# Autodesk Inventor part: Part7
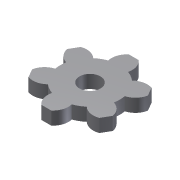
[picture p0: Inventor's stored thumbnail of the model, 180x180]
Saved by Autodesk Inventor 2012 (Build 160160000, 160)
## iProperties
Shininess: 77.0
Angle Display Precision: 2
Document Length Units: 11269
Document Angle Units: 11279
Document Time Units: 11290
Document Mass Units: 11283
Document Length Units Precision: 3
Document Angle Units Precision: 2
Created: 2002-01
Part Number: Part7
Document SubType Name: Modeling
Designer: ***
Density: 1 g/cm^3
Material: Default
Density: 0.0
Volumn: 0.0
Area: 0.0
PropertySet Name: Model Information
Control State: 0
Master: False
Checked Out: False
Author: ***
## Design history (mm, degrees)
sketch "Sketch1"
  geometry: L1 (-3.771, 33.333)-(3.771, 33.333); L2 (-30.753, 13.401)-(-26.982, 19.933); L3 (-30.753, -13.401)-(-26.982, -19.933); L4 (-3.771, -33.333)-(3.771, -33.333); L5 (30.753, 13.401)-(26.982, 19.933); L6 (30.753, -13.401)-(26.982, -19.933); C1 r 8 at (0, 0); A1 r 11.863 centre (3.952, 24.328) between (-3.771, 33.333) and (-7.559, 21.457); A2 r 11.863 centre (-3.952, 24.328) between (7.559, 21.457) and (3.771, 33.333); A3 r 11.863 centre (-19.093, 15.587) between (-30.753, 13.401) and (-22.362, 4.182); A4 r 11.863 centre (-23.045, 8.742) between (-14.803, 17.275) and (-26.982, 19.933); A5 r 22.749 centre (0, 0) between (-7.559, 21.457) and (-14.803, 17.275); A6 r 11.863 centre (-23.045, -8.742) between (-26.982, -19.933) and (-14.803, -17.275); A7 r 11.863 centre (-19.093, -15.587) between (-22.362, -4.182) and (-30.753, -13.401); A8 r 11.863 centre (3.952, -24.328) between (-7.559, -21.457) and (-3.771, -33.333); A9 r 11.863 centre (-3.952, -24.328) between (3.771, -33.333) and (7.559, -21.457); A10 r 11.863 centre (23.045, 8.742) between (26.982, 19.933) and (14.803, 17.275); A11 r 11.863 centre (19.093, 15.587) between (22.362, 4.182) and (30.753, 13.401); A12 r 11.863 centre (19.093, -15.587) between (30.753, -13.401) and (22.362, -4.182); A13 r 11.863 centre (23.045, -8.742) between (14.803, -17.275) and (26.982, -19.933); A14 r 22.749 centre (0, 0) between (-22.362, 4.182) and (-22.362, -4.182); A15 r 22.749 centre (0, 0) between (-14.803, -17.275) and (-7.559, -21.457); A16 r 22.749 centre (0, 0) between (7.559, -21.457) and (14.803, -17.275); A17 r 22.749 centre (0, 0) between (22.362, -4.182) and (22.362, 4.182); A18 r 22.749 centre (0, 0) between (14.803, 17.275) and (7.559, 21.457)
  constraints: 36 point on circle, 19 centre point, 12 end point, 1 coincident
  dimensions: "d2" = 16 diameter of C1
extrude "Extrusion1" new body sketch "Sketch1" distance "d0" = 10; taper "d1" = 0 deg
body "Solid1"
